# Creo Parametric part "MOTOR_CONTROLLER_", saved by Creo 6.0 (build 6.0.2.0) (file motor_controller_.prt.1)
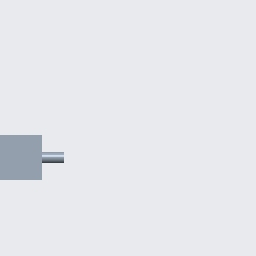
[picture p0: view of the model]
Units: Inch lbm Second (Pro/E Default); INCH, POUND, SECS

Created from: INLBS_PART_SOLID.PRT

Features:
  1. datum plane "RIGHT"
  2. datum plane "TOP"
  3. datum plane "FRONT"
  4. coordinate system
  5. sketch "Sketch 1"
  6. extrusion "Extrude 1"
  7. sketch "Sketch 2"
  8. extrusion "Extrude 2"

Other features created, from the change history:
  component interface "Component Interface id 133"
  component interface "Component Interface id 134"

Surfaces: 8 plane, 2 cylinder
